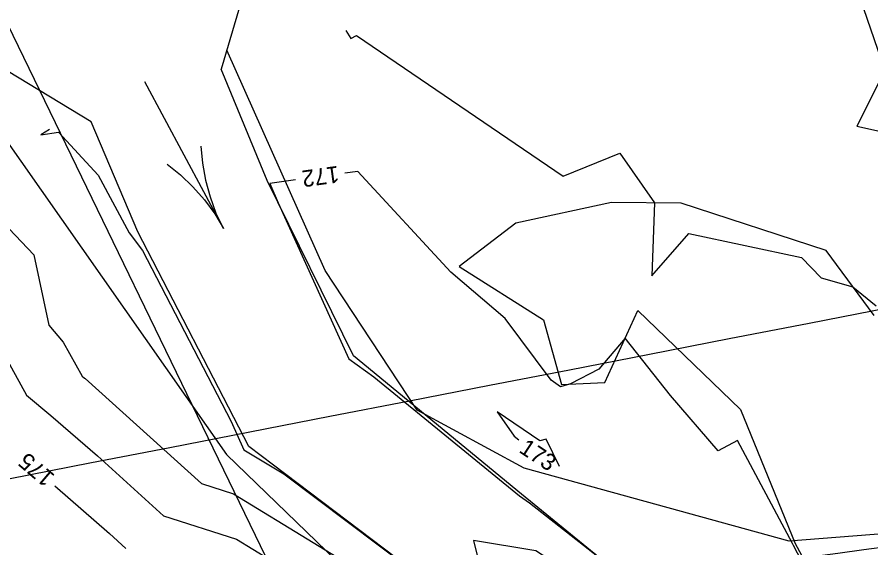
# Model space of a CAD drawing. Extents: x 2086416 to 2115205, y 575507 to 632762.
# Drawn here: x 2111454.1 to 2111556.7, y 581686.3 to 581750.1 of the extents above; entities that cross this region are included whole.
import ezdxf

# ---------------------------------------------------------------- set-up
doc = ezdxf.new("R2010")
doc.units = 0
for name, color, linetype in [('DTM Contours Major', 7, 'Continuous'), ('DTM Contours Major Text', 7, 'Continuous'), ('DTM Contours Minor', 7, 'Continuous'), ('DTM Contours Minor Text', 7, 'Continuous'), ('Exist Hydro River Flow Arrow CELL', 7, 'Continuous'), ('Exist Hydro Stream or Body of Water', 7, 'Continuous'), ('Exist Hydrographic FEMA Cross Section', 7, 'Continuous'), ('Exist Right of Way Line', 7, 'Continuous'), ('Exist Vegetation Woods Line', 7, 'Continuous'), ('Prop Horizontal Alignment Station Label', 7, 'Continuous')]:
    doc.layers.add(name, color=color, linetype=linetype)

msp = doc.modelspace()

# ---------------------------------------------------------------- linework, layer by layer
at = {"layer": 'DTM Contours Major'}
msp.add_lwpolyline([(2111458.61, 581693.73), (2111465.19, 581688.01), (2111467.15, 581686.23)], dxfattribs=at)
at = {"layer": 'DTM Contours Minor'}
for points in [[(2111512.86, 581775.08), (2111525.32, 581775.7), (2111541.08, 581770.28), (2111542.43, 581768.36), (2111544.24, 581768.53), (2111554.95, 581753.72), (2111558.4, 581743.64), (2111555.04, 581736.97), (2111563.15, 581735.16)], [(2111493.59, 581748.45), (2111494.22, 581747.49), (2111494.87, 581747.84), (2111519.72, 581730.97), (2111526.54, 581733.72), (2111530.69, 581727.73), (2111530.4, 581718.98), (2111534.84, 581724.07), (2111548.37, 581721.16), (2111550.74, 581718.74), (2111554.56, 581717.65), (2111557.36, 581715.39)], [(2111457.98, 581736.54), (2111456.92, 581735.92), (2111459.05, 581736.25), (2111463.83, 581731.09), (2111467.55, 581724.13), (2111469.15, 581722.04), (2111479.82, 581701.48), (2111481.33, 581698.06), (2111486.15, 581695.2), (2111501.55, 581683.63)], [(2111548.2, 581671.64), (2111548.49, 581671.78), (2111551.1, 581675.47), (2111552.12, 581677.61), (2111547.4, 581686.58), (2111547.31, 581686.83), (2111540.68, 581699.19), (2111538.37, 581697.96), (2111532.61, 581704.59), (2111527.17, 581711.48), (2111524.03, 581707.75), (2111520.62, 581705.98), (2111519.42, 581705.65), (2111518.28, 581706.43), (2111512.75, 581713.86), (2111506.23, 581719.41), (2111495.05, 581731.52), (2111493.49, 581731.31)], [(2111487.55, 581730.5), (2111484.48, 581730.08), (2111485.47, 581727.76), (2111493.95, 581708.99), (2111496.97, 581706.84), (2111514.48, 581692.55), (2111515.67, 581691.69), (2111524.2, 581685.01), (2111533.54, 581678.42), (2111534.65, 581678.5), (2111535.24, 581677.74), (2111541.52, 581673.5), (2111544.74, 581671.76), (2111547.52, 581671.58), (2111548.2, 581671.64)], [(2111453.11, 581724.62), (2111456.1, 581721.51), (2111457.9, 581713.03), (2111459.62, 581711.02), (2111461.92, 581706.93), (2111462.2, 581706.7), (2111462.27, 581706.64), (2111476.24, 581694.01), (2111480.08, 581692.79), (2111499.23, 581681.07)], [(2111452.73, 581709.15), (2111455.2, 581704.64), (2111458.13, 581702.19), (2111463.73, 581697.33), (2111471.7, 581690.12), (2111480.45, 581687.34), (2111494.21, 581678.92)], [(2111516.93, 581699.16), (2111511.81, 581702.65), (2111513.85, 581699.7), (2111514.38, 581699.27)], [(2111519.3, 581696.05), (2111517.68, 581699.36), (2111516.93, 581699.16)], [(2111557.83, 581661.46), (2111555.52, 581665.51), (2111555.37, 581667.47), (2111555.16, 581669.32), (2111552.73, 581668.07), (2111549.51, 581667.79), (2111543.48, 581666.56), (2111541.67, 581668.03), (2111535.66, 581672.43), (2111532.64, 581674.52), (2111531.72, 581675.14), (2111527.67, 581678.31), (2111522.75, 581681.84), (2111516.46, 581685.95), (2111508.95, 581687.16), (2111510.22, 581682)]]:
    msp.add_lwpolyline(points, dxfattribs=at)
at = {"layer": 'Exist Hydro River Flow Arrow CELL'}
for p, q in [((2111478.89, 581724.66), (2111469.43, 581742.29)), ((2111476.17, 581734.56), (2111476.37, 581732.52)), ((2111474.16, 581733.47), (2111474.16, 581733.47)), ((2111472.14, 581732.39), (2111473.73, 581731.1)), ((2111476.37, 581732.52), (2111476.74, 581730.48)), ((2111473.73, 581731.1), (2111475.22, 581729.66)), ((2111476.74, 581730.48), (2111477.29, 581728.46)), ((2111475.22, 581729.66), (2111476.61, 581728.09)), ((2111476.61, 581728.09), (2111477.85, 581726.43)), ((2111477.29, 581728.46), (2111477.98, 581726.5)), ((2111477.85, 581726.43), (2111478.89, 581724.66)), ((2111477.98, 581726.5), (2111478.89, 581724.66))]:
    msp.add_line(p, q, dxfattribs=at)
at = {"layer": 'Exist Hydro Stream or Body of Water'}
for points in [[(2111463, 581737.48), (2111415.11, 581766.53), (2111397.64, 581820.96), (2111352.3, 581841.23), (2111333.83, 581869.49), (2111330, 581879.12), (2111337.82, 581902), (2111329.78, 581919.05), (2111313.88, 581938.09), (2111294.11, 581978.61), (2111295.93, 582000.43), (2111293.88, 582015.55), (2111285.78, 582045.07), (2111284.37, 582067.54), (2111288.67, 582094.58), (2111287.89, 582112.99), (2111281.07, 582150.07), (2111274.06, 582190.6)], [(2111453.09, 582094.1), (2111443.96, 582082.97), (2111447.94, 582071.29), (2111430.65, 582047.36), (2111437.21, 582014.64), (2111436.6, 581990.7), (2111456.37, 581961.91), (2111482.37, 581945.66), (2111482.01, 581910.08), (2111498.18, 581892.27), (2111507.18, 581840.49), (2111478.63, 581743.8)], [(2111557.1, 581714.2), (2111551.35, 581722.03), (2111533.92, 581727.7), (2111525.55, 581727.77), (2111514.02, 581725.29), (2111507.22, 581720.09), (2111517.38, 581713.7), (2111519.53, 581705.93), (2111524.72, 581706.16), (2111528.7, 581714.8), (2111541.06, 581702.9), (2111547.6, 581686.8), (2111552.73, 581677.36), (2111547.95, 581671.83), (2111544.85, 581671.93), (2111533.91, 581677.08), (2111514.73, 581692.74), (2111494.53, 581709.36), (2111484.15, 581730.44), (2111478.63, 581743.8)], [(2111591.59, 581574.69), (2111583.51, 581582.32), (2111586.65, 581587.28), (2111586.9, 581588.76), (2111586.51, 581589.98), (2111561.57, 581606.34), (2111549, 581629.07), (2111542.47, 581641.26), (2111541.35, 581641.18), (2111528.82, 581652.89), (2111524.36, 581663.91), (2111523.31, 581667.75), (2111502.68, 581682.78), (2111481.94, 581698.46), (2111468.58, 581724.28), (2111463, 581737.48)]]:
    msp.add_lwpolyline(points, dxfattribs=at)
at = {"layer": 'Exist Hydrographic FEMA Cross Section'}
msp.add_lwpolyline([(2111558.92, 581715.13), (2111549.31, 581713.26), (2111539.7, 581711.4), (2111530.09, 581709.53), (2111520.48, 581707.66), (2111510.88, 581705.79), (2111501.27, 581703.93), (2111491.66, 581702.06), (2111482.06, 581700.19), (2111472.45, 581698.32), (2111462.84, 581696.46), (2111453.23, 581694.59), (2111443.62, 581692.72), (2111434.02, 581690.85), (2111424.41, 581688.98), (2111414.8, 581687.11), (2111405.19, 581685.25), (2111395.59, 581683.38), (2111385.98, 581681.51), (2111376.37, 581679.64), (2111366.77, 581677.77), (2111357.16, 581675.91), (2111347.55, 581674.04)], dxfattribs=at)
at = {"layer": 'Exist Right of Way Line'}
msp.add_arc((2108326.55, 606231.5), 24756.94, 277.393911, 277.856215, dxfattribs=at)
at = {"layer": 'Exist Vegetation Woods Line'}
for points in [[(2112042.22, 581740.22), (2112007.09, 581741.23), (2111957.14, 581737.86), (2111908.66, 581731.85), (2111808.65, 581718.24), (2111760.41, 581712.7), (2111710.34, 581706.77), (2111661.65, 581697.22), (2111616.66, 581692.44), (2111575, 581689.29), (2111546.91, 581687.08), (2111515.04, 581695.86), (2111502.17, 581702.85), (2111491.11, 581719.62), (2111479.28, 581746.11)], [(2111452.1, 581736.22), (2111479.27, 581697.5), (2111499.68, 581677.78), (2111492.04, 581671.34), (2111416.64, 581665.13), (2111367.28, 581660.93), (2111318.17, 581654.2), (2111268.32, 581650.61), (2111220.66, 581649.45), (2111173.29, 581649.12), (2111125.98, 581651.57), (2111078.27, 581655.72), (2111059.79, 581657.65)]]:
    msp.add_lwpolyline(points, dxfattribs=at)
at = {"layer": 'Prop Horizontal Alignment Station Label'}
msp.add_line((2111502.04, 581648.05), (2111433.3, 581789.66), dxfattribs=at)

# ---------------------------------------------------------------- texts
at = {"layer": 'DTM Contours Major Text'}
msp.add_text('175', height=2, rotation=139.5891, dxfattribs=at).set_placement((2111458.73, 581694.98))
at = {"layer": 'DTM Contours Minor Text'}
for s, rotation, p in [('172', 187.7686, (2111492.64, 581732.2)), ('173', 326.7687, (2111514.3, 581697.85))]:
    msp.add_text(s, height=2, rotation=rotation, dxfattribs=at).set_placement(p)

doc.saveas('drawing.dxf')
